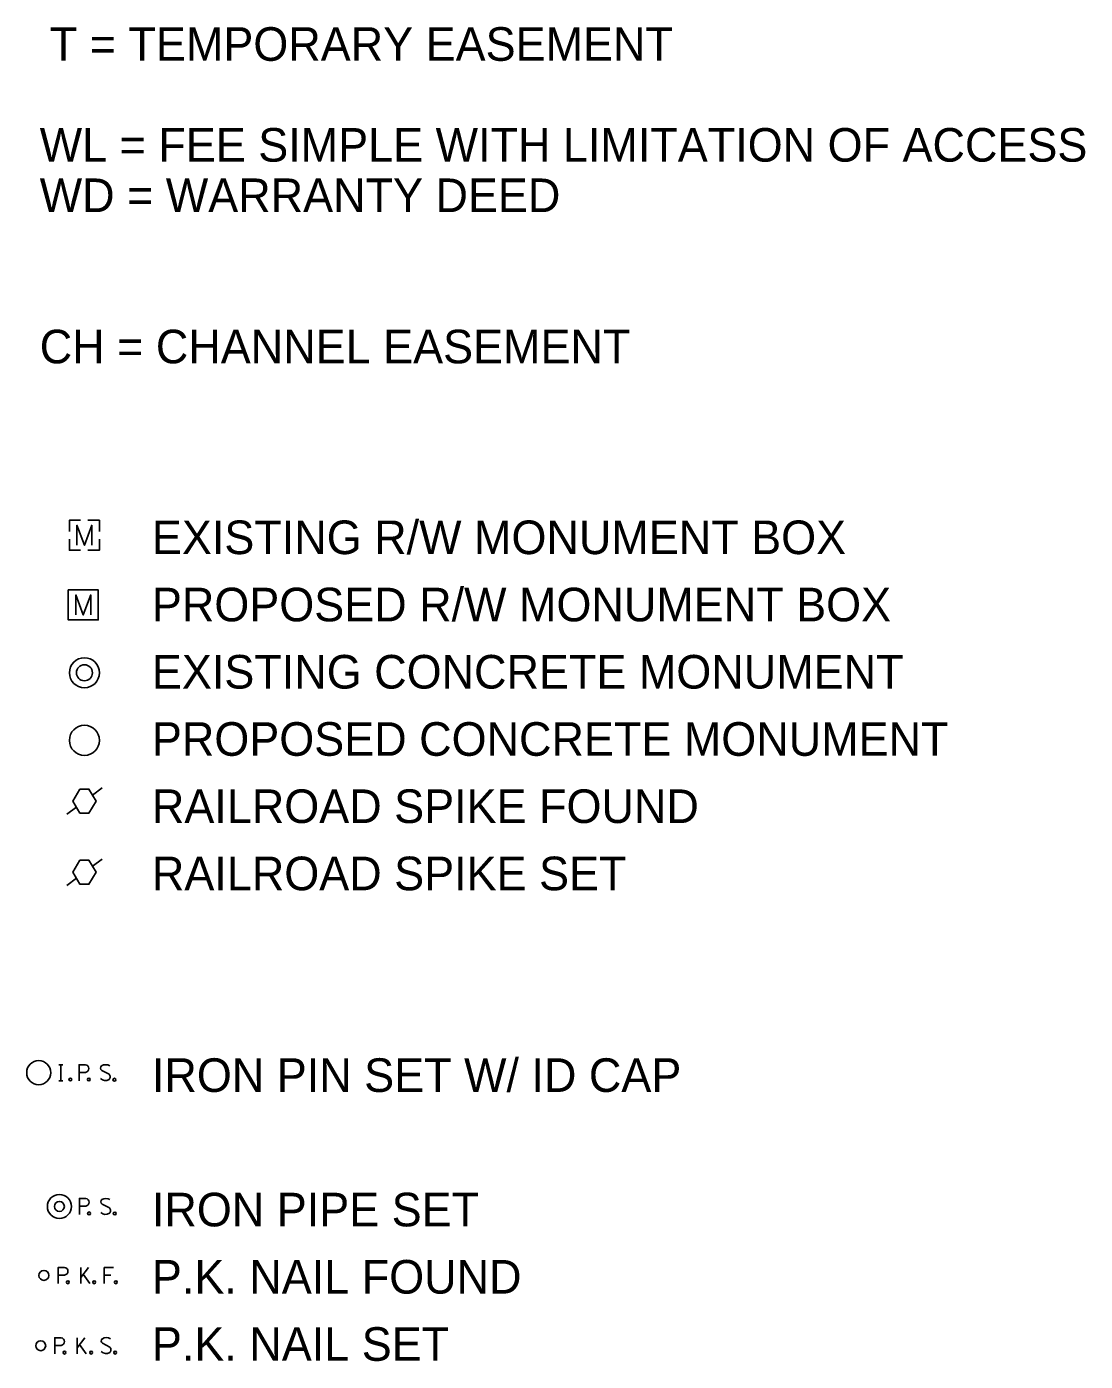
# Model space of a CAD drawing. Extents: x -13.9 to 69.1, y -25.2 to 26.1.
# Drawn here: x 36.85 to 41.26, y 9.04 to 14.6 of the extents above; entities that cross this region are included whole.
import ezdxf

# ---------------------------------------------------------------- set-up
doc = ezdxf.new("R2010")
doc.units = 0
doc.layers.add('SH_Text', color=7, linetype='Continuous')

msp = doc.modelspace()

# ---------------------------------------------------------------- linework, layer by layer
at = {"layer": 'SH_Text'}
for p, q in [((37.0935, 12.4832), (37.0935, 12.4832)), ((37.0888, 12.1928), (37.0888, 12.1928)), ((37.1671, 11.4313), (37.1271, 11.4013)), ((37.06, 11.3513), (37.0199, 11.3215)), ((37.1671, 11.1343), (37.1271, 11.1043)), ((37.06, 11.0543), (37.0199, 11.0245)), ((36.9864, 10.2781), (37.0031, 10.2781)), ((36.9864, 10.2781), (37.0031, 10.2781)), ((36.9947, 10.2114), (36.9947, 10.2781)), ((37.0714, 10.2462), (37.0981, 10.2462)), ((37.1657, 10.2543), (37.1962, 10.2385)), ((36.9864, 10.2114), (37.0031, 10.2114)), ((37.0726, 9.689), (37.0993, 9.689)), ((37.167, 9.6972), (37.1976, 9.6813)), ((36.9845, 9.4018), (37.0112, 9.4018)), ((37.078, 9.3671), (37.078, 9.4338)), ((37.078, 9.3913), (37.11, 9.4338)), ((37.0883, 9.405), (37.1158, 9.3671)), ((37.1763, 9.3671), (37.1763, 9.4338)), ((37.1763, 9.4338), (37.2148, 9.4338)), ((37.1763, 9.4013), (37.2037, 9.4013)), ((37.0629, 9.0742), (37.0629, 9.1408)), ((37.0629, 9.0983), (37.0949, 9.1408)), ((37.1687, 9.1175), (37.1993, 9.1017)), ((36.9703, 9.1089), (36.9969, 9.1089)), ((37.0733, 9.1121), (37.1008, 9.0742))]:
    msp.add_line(p, q, dxfattribs=at)
for points in [[(37.031, 12.4991), (37.031, 12.5458), (37.0778, 12.5458)], [(37.0626, 12.4416), (37.0626, 12.5249), (37.0935, 12.4416), (37.1243, 12.5249), (37.1243, 12.4416)], [(37.1083, 12.5458), (37.1561, 12.5458), (37.1561, 12.4991)], [(37.0778, 12.4207), (37.031, 12.4207), (37.031, 12.4675)], [(37.1561, 12.4675), (37.1561, 12.4207), (37.1083, 12.4207)], [(37.0263, 12.2554), (37.1514, 12.2554), (37.1514, 12.1303), (37.0263, 12.1303), (37.0263, 12.2554)], [(37.058, 12.1511), (37.058, 12.2345), (37.0888, 12.1511), (37.1196, 12.2345), (37.1196, 12.1511)], [(37.0981, 10.2781), (37.0714, 10.2781), (37.0714, 10.2114)], [(37.0993, 9.7209), (37.0726, 9.7209), (37.0726, 9.6543)], [(37.0112, 9.4338), (36.9845, 9.4338), (36.9845, 9.3671)], [(36.9969, 9.1408), (36.9703, 9.1408), (36.9703, 9.0742)]]:
    msp.add_lwpolyline(points, dxfattribs=at)
for points in [[(37.0747, 11.4263), (37.1122, 11.4263), (37.1418, 11.3763), (37.1122, 11.3263), (37.0747, 11.3263), (37.0451, 11.3763)], [(37.0747, 11.1293), (37.1122, 11.1293), (37.1418, 11.0793), (37.1122, 11.0293), (37.0747, 11.0293), (37.0451, 11.0793)]]:
    msp.add_lwpolyline(points, close=True, dxfattribs=at)
for centre, radius in [((37.0935, 11.9105), 0.0625), ((37.0935, 11.9105), 0.0333), ((37.0935, 11.629), 0.0625), ((36.9031, 10.2448), 0.05), ((37.0349, 10.216), 0.00583), ((37.1116, 10.216), 0.00583), ((37.2184, 10.2155), 0.00583), ((36.9893, 9.6876), 0.05), ((36.9893, 9.6876), 0.0208), ((37.1128, 9.6588), 0.00583), ((37.2197, 9.6584), 0.00583), ((36.9246, 9.4004), 0.0207), ((37.0246, 9.3716), 0.00583), ((37.1343, 9.3716), 0.00583), ((37.2245, 9.3716), 0.00583), ((36.9117, 9.1075), 0.0206), ((37.0104, 9.0787), 0.00583), ((37.1214, 9.0787), 0.00583), ((37.2214, 9.0787), 0.00583)]:
    msp.add_circle(centre, radius, dxfattribs=at)
for centre, radius, start, end in [((37.0956, 10.2621), 0.0162, 278.8803, 81.1197), ((37.1723, 10.2642), 0.0118, 126.2587, 236.3675), ((37.182, 10.2431), 0.0349, 61.3463, 118.6537), ((37.1864, 10.2275), 0.0148, 311.4883, 47.9358), ((37.1806, 10.2392), 0.0276, 223.6695, 304.3963), ((37.0969, 9.705), 0.0162, 278.8803, 81.1197), ((37.1735, 9.707), 0.0118, 126.2587, 236.3675), ((37.1832, 9.6859), 0.0349, 61.3463, 118.6537), ((37.1876, 9.6704), 0.0148, 311.4883, 47.9358), ((37.1818, 9.6821), 0.0276, 223.6695, 304.3963), ((37.0087, 9.4178), 0.0162, 278.8803, 81.1197), ((36.9944, 9.1249), 0.0162, 278.8803, 81.1197), ((37.1752, 9.1274), 0.0118, 126.2587, 236.3675), ((37.185, 9.1062), 0.0349, 61.3463, 118.6537), ((37.1836, 9.1024), 0.0276, 223.6695, 304.3963), ((37.1894, 9.0907), 0.0148, 311.4883, 47.9358)]:
    msp.add_arc(centre, radius, start, end, dxfattribs=at)

# ---------------------------------------------------------------- texts
for s, p in [('T = TEMPORARY EASEMENT', (36.9493, 14.4593)), ('WL = FEE SIMPLE WITH LIMITATION OF ACCESS', (36.9073, 14.0392)), ('WD = WARRANTY DEED', (36.9073, 13.8292)), ('CH = CHANNEL EASEMENT', (36.9073, 13.1992)), ('EXISTING R/W MONUMENT BOX', (37.3746, 12.4046)), ('PROPOSED R/W MONUMENT BOX', (37.3746, 12.1246)), ('EXISTING CONCRETE MONUMENT', (37.3746, 11.8446)), ('PROPOSED CONCRETE MONUMENT', (37.3746, 11.5646)), ('RAILROAD SPIKE FOUND', (37.3746, 11.2846)), ('RAILROAD SPIKE SET', (37.3746, 11.0046)), ('IRON PIN SET W/ ID CAP', (37.3746, 10.1646)), ('IRON PIPE SET', (37.3746, 9.6046)), ('P.K. NAIL FOUND', (37.3746, 9.3246)), ('P.K. NAIL SET', (37.3746, 9.0446))]:
    msp.add_text(s, height=0.14, dxfattribs=at).set_placement(p)

doc.saveas('drawing.dxf')
